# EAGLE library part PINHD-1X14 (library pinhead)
PIN HEADER
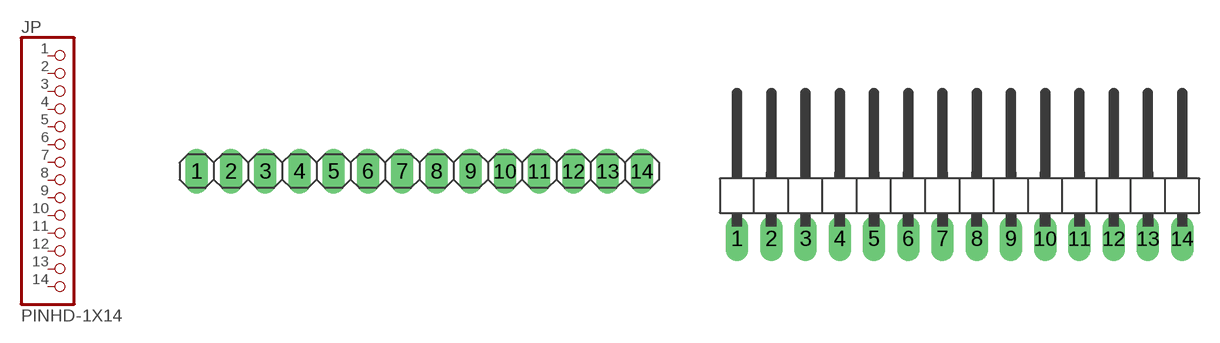
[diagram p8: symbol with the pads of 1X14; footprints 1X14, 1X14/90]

Designator prefix JP

## PINHD-1X14  [1X14]
1  1  pas
2  2  pas
3  3  pas
4  4  pas
5  5  pas
6  6  pas
7  7  pas
8  8  pas
9  9  pas
10  10  pas
11  11  pas
12  12  pas
13  13  pas
14  14  pas

## PINHD-1X14/90  [1X14/90]
Pads as for 1X14

## Footprint 1X14 (pad centres in mm)
PIN HEADER
drill 1.016 pad 1.67 long: 1 -16.51,0; 2 -13.97,0; 3 -11.43,0; 4 -8.89,0; 5 -6.35,0; 6 -3.81,0; 7 -1.27,0; 8 1.27,0; 9 3.81,0; 10 6.35,0; 11 8.89,0; 12 11.43,0; 13 13.97,0; 14 16.51,0

## Footprint 1X14/90 (pad centres in mm)
PIN HEADER
drill 1.016 pad 1.67 long: 1 -16.51,-3.81; 2 -13.97,-3.81; 3 -11.43,-3.81; 4 -8.89,-3.81; 5 -6.35,-3.81; 6 -3.81,-3.81; 7 -1.27,-3.81; 8 1.27,-3.81; 9 3.81,-3.81; 10 6.35,-3.81; 11 8.89,-3.81; 12 11.43,-3.81; 13 13.97,-3.81; 14 16.51,-3.81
